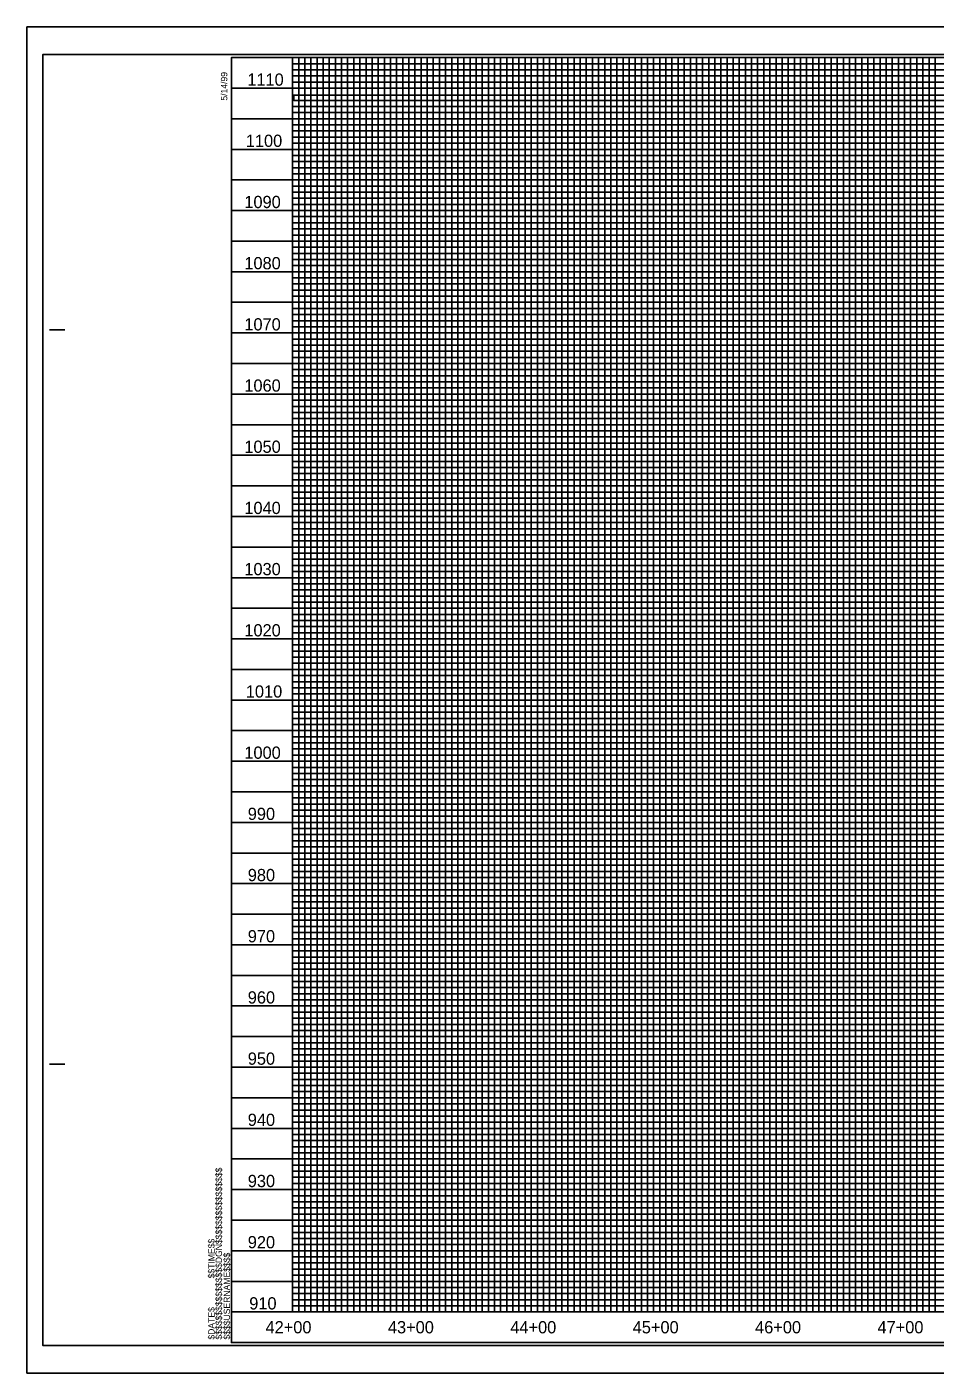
# Model space of a CAD drawing. Extents: x 1263639 to 1265460, y 747271 to 748371.
# Drawn here: x 1263639 to 1264381, y 747271 to 748371 of the extents above; entities that cross this region are included whole.
import ezdxf

# ---------------------------------------------------------------- set-up
doc = ezdxf.new("R2010")
doc.units = 0
for name, color, linetype in [('Pattern 1', 7, 'Continuous'), ('Pattern 2', 7, 'Continuous'), ('Prop Drainage Structure Bridge Opening', 7, 'Continuous'), ('Prop Grid Mask', 7, 'Continuous'), ('Prop Horizontal Alignment Curve and Spiral Data', 7, 'Continuous'), ('Prop Paved Shoulder', 7, 'Continuous'), ('Prop PFL Text', 7, 'Continuous'), ('Prop Roadway Bridge', 7, 'Continuous'), ('Prop Terminator CELL', 7, 'Continuous'), ('Prop Vertical Profile Strip Grade', 7, 'Continuous'), ('Prop VPI Label', 7, 'Continuous'), ('Sheet Sticker Exception Certification CELL', 7, 'Continuous')]:
    doc.layers.add(name, color=color, linetype=linetype)

msp = doc.modelspace()

# ---------------------------------------------------------------- linework, layer by layer
at = {"layer": 'Pattern 1'}
for points in [[(1263805.8, 748345.7), (1263855.8, 748345.7), (1263855.8, 747320.7), (1263905.8, 747320.7), (1263905.8, 748345.7), (1263955.8, 748345.7), (1263955.8, 747320.7), (1264005.8, 747320.7), (1264005.8, 748345.7), (1264055.8, 748345.7), (1264055.8, 747320.7), (1264105.8, 747320.7), (1264105.8, 748345.7), (1264155.8, 748345.7), (1264155.8, 747320.7), (1264205.8, 747320.7), (1264205.8, 748345.7), (1264255.8, 748345.7), (1264255.8, 747320.7), (1264305.8, 747320.7), (1264305.8, 748345.7), (1264355.8, 748345.7), (1264355.8, 747320.7), (1264405.8, 747320.7)], [(1265105.7, 748270.7), (1263805.9, 748270.7), (1263805.9, 748320.7), (1265005.8, 748320.7)], [(1265305.8, 748170.7), (1263805.8, 748170.7), (1263805.8, 748220.7), (1265105.7, 748220.7)], [(1265305.8, 748070.7), (1263805.8, 748070.7), (1263805.8, 748120.7), (1265305.8, 748120.7)], [(1265305.8, 747970.7), (1263805.8, 747970.7), (1263805.8, 748020.7), (1265305.8, 748020.7)], [(1265305.8, 747870.7), (1263805.8, 747870.7), (1263805.8, 747920.7), (1265305.8, 747920.7)], [(1265305.8, 747770.7), (1263805.8, 747770.7), (1263805.8, 747820.7), (1265305.8, 747820.7)], [(1265305.8, 747670.7), (1263805.8, 747670.7), (1263805.8, 747720.7), (1265305.8, 747720.7)], [(1265305.8, 747570.7), (1263805.8, 747570.7), (1263805.8, 747620.7), (1265305.8, 747620.7)], [(1265305.8, 747470.7), (1263805.8, 747470.7), (1263805.8, 747520.7), (1265305.8, 747520.7)], [(1265305.8, 747370.7), (1263805.8, 747370.7), (1263805.8, 747420.7), (1265305.8, 747420.7)]]:
    msp.add_lwpolyline(points, dxfattribs=at)
at = {"layer": 'Pattern 2'}
for points in [[(1263880.8, 747320.7), (1263880.8, 748345.7), (1263930.8, 748345.7), (1263930.8, 747320.7), (1263980.8, 747320.7), (1263980.8, 748345.7), (1264030.8, 748345.7), (1264030.8, 747320.7), (1264080.8, 747320.7), (1264080.8, 748345.7), (1264130.8, 748345.7), (1264130.8, 747320.7), (1264180.8, 747320.7), (1264180.8, 748345.7), (1264230.8, 748345.7), (1264230.8, 747320.7), (1264280.8, 747320.7), (1264280.8, 748345.7), (1264330.8, 748345.7), (1264330.8, 747320.7), (1264380.8, 747320.7), (1264380.8, 748345.7), (1264430.8, 748345.7)], [(1263805.8, 748295.7), (1265105.7, 748295.7)], [(1265105.7, 748245.7), (1263805.8, 748245.7), (1263805.8, 748195.7), (1265105.7, 748195.7)], [(1265305.8, 748145.7), (1263805.8, 748145.7), (1263805.8, 748095.7), (1265305.8, 748095.7)], [(1265305.8, 748045.7), (1263805.8, 748045.7), (1263805.8, 747995.7), (1265305.8, 747995.7)], [(1265305.8, 747945.7), (1263805.8, 747945.7), (1263805.8, 747895.7), (1265305.8, 747895.7)], [(1265305.8, 747845.7), (1263805.8, 747845.7), (1263805.8, 747795.7), (1265305.8, 747795.7)], [(1265305.8, 747745.7), (1263805.8, 747745.7), (1263805.8, 747695.7), (1265305.8, 747695.7)], [(1265305.8, 747645.7), (1263805.8, 747645.7), (1263805.8, 747595.7), (1265305.8, 747595.7)], [(1265305.8, 747545.7), (1263805.8, 747545.7), (1263805.8, 747495.7), (1265305.8, 747495.7)], [(1265305.8, 747445.7), (1263805.8, 747445.7), (1263805.8, 747395.7), (1265305.8, 747395.7)], [(1265305.8, 747345.7), (1263805.8, 747345.7)]]:
    msp.add_lwpolyline(points, dxfattribs=at)
at = {"layer": 'Prop Drainage Structure Bridge Opening'}
for p, q in [((1265322.8, 748370.7), (1263638.8, 748370.7)), ((1263638.8, 748370.7), (1263638.8, 747270.7)), ((1263638.8, 747270.7), (1265322.8, 747270.7))]:
    msp.add_line(p, q, dxfattribs=at)
at = {"layer": 'Prop Grid Mask'}
msp.add_lwpolyline([(1263855.8, 748345.7), (1265105.7, 748345.7), (1265105.8, 747320.7), (1263855.8, 747320.7)], close=True, dxfattribs=at)
at = {"layer": 'Prop Paved Shoulder'}
for p, q in [((1263657.3, 748123.2), (1263669.8, 748123.2)), ((1263657.3, 747523.2), (1263669.8, 747523.2)), ((1265305.8, 747320.7), (1263805.8, 747320.7)), ((1263805.8, 747295.7), (1263805.8, 747295.7)), ((1263805.8, 747295.7), (1263805.8, 747295.7)), ((1263805.8, 747295.7), (1263805.8, 747295.7)), ((1263805.8, 747295.7), (1263805.8, 747295.7)), ((1263805.8, 747295.7), (1263805.8, 747295.7)), ((1263805.8, 747295.7), (1263805.8, 747295.7))]:
    msp.add_line(p, q, dxfattribs=at)
msp.add_lwpolyline([(1265305.8, 748345.7), (1263805.8, 748345.7), (1263805.8, 747295.7), (1265305.8, 747295.7)], close=True, dxfattribs=at)
msp.add_lwpolyline([(1263843.3, 747295.7), (1263843.3, 747295.7)], dxfattribs=at)
at = {"layer": 'Prop PFL Text'}
for p, q in [((1263855.8, 748345.7), (1263855.8, 747320.7)), ((1263905.8, 748345.7), (1263905.8, 747320.7)), ((1263955.8, 748345.7), (1263955.8, 747320.7)), ((1264005.8, 748345.7), (1264005.8, 747320.7)), ((1264055.8, 748345.7), (1264055.8, 747320.7)), ((1264105.8, 748345.7), (1264105.8, 747320.7)), ((1264155.8, 748345.7), (1264155.8, 747320.7)), ((1264205.8, 748345.7), (1264205.8, 747320.7)), ((1264255.8, 748345.7), (1264255.8, 747320.7)), ((1264305.8, 748345.7), (1264305.8, 747320.7)), ((1264355.8, 748345.7), (1264355.8, 747320.7)), ((1263805.8, 748320.7), (1265005.8, 748320.7)), ((1263805.8, 748270.7), (1265105.7, 748270.7)), ((1263805.8, 748220.7), (1265105.7, 748220.7)), ((1263805.8, 748170.7), (1265305.8, 748170.7)), ((1263805.8, 748120.7), (1265305.8, 748120.7)), ((1263805.8, 748070.7), (1265305.8, 748070.7)), ((1263805.8, 748020.7), (1265305.8, 748020.7)), ((1263805.8, 747970.7), (1265305.8, 747970.7)), ((1263805.8, 747920.7), (1265305.8, 747920.7)), ((1263805.8, 747870.7), (1265305.8, 747870.7)), ((1263805.8, 747820.7), (1265305.8, 747820.7)), ((1263805.8, 747770.7), (1265305.8, 747770.7)), ((1263805.8, 747720.7), (1265305.8, 747720.7)), ((1263805.8, 747670.7), (1265305.8, 747670.7)), ((1263805.8, 747620.7), (1265305.8, 747620.7)), ((1263805.8, 747570.7), (1265305.8, 747570.7)), ((1263805.8, 747520.7), (1265305.8, 747520.7)), ((1263805.8, 747470.7), (1265305.8, 747470.7)), ((1263805.8, 747420.7), (1265305.8, 747420.7)), ((1263805.8, 747370.7), (1265305.8, 747370.7))]:
    msp.add_line(p, q, dxfattribs=at)
at = {"layer": 'Prop Roadway Bridge'}
msp.add_line((1263805.8, 747295.7), (1263805.8, 747295.7), dxfattribs=at)
at = {"layer": 'Prop Terminator CELL'}
msp.add_lwpolyline([(1265318.3, 748348.3), (1263651.8, 748348.3), (1263651.8, 747293.2), (1265318.3, 747293.2)], close=True, dxfattribs=at)
at = {"layer": 'Prop VPI Label'}
msp.add_lwpolyline([(1265322.8, 748370.7), (1263638.8, 748370.7), (1263638.8, 747270.7), (1265322.8, 747270.7)], close=True, dxfattribs=at)
at = {"layer": 'Sheet Sticker Exception Certification CELL'}
for p, q in [((1265255.8, 748165.7), (1263855.8, 748165.7)), ((1263855.8, 748165.7), (1263855.8, 748160.7)), ((1263855.8, 748160.7), (1265255.8, 748160.7)), ((1265255.8, 748140.7), (1263855.8, 748140.7))]:
    msp.add_line(p, q, dxfattribs=at)
for points in [[(1263860.8, 748345.7), (1263865.8, 748345.7), (1263870.8, 748345.7), (1263875.8, 748345.7), (1263885.8, 748345.7), (1263852.7, 748345.7), (1263857.7, 748345.7), (1263815.8, 748345.7), (1263820.8, 748345.7), (1263825.8, 748345.7), (1263835.8, 748345.7), (1263840.8, 748345.7), (1263845.8, 748345.7), (1263850.8, 748345.7), (1263860.8, 748345.7), (1263860.8, 747320.7), (1263865.8, 747320.7), (1263865.8, 748345.7), (1263870.8, 748345.7), (1263870.8, 747320.7), (1263875.8, 747320.7), (1263875.8, 748345.7), (1263885.8, 748345.7), (1263885.8, 747320.7), (1263890.8, 747320.7), (1263890.8, 748345.7), (1263895.8, 748345.7), (1263895.8, 747320.7), (1263900.8, 747320.7), (1263900.8, 748345.7), (1263910.8, 748345.7), (1263910.8, 747320.7), (1263915.8, 747320.7), (1263915.8, 748345.7), (1263920.8, 748345.7), (1263920.8, 747320.7), (1263925.8, 747320.7), (1263925.8, 748345.7), (1263935.8, 748345.7), (1263935.8, 747320.7), (1263940.8, 747320.7), (1263940.8, 748345.7), (1263945.8, 748345.7), (1263945.8, 747320.7), (1263950.8, 747320.7), (1263950.8, 748345.7), (1263960.8, 748345.7), (1263960.8, 747320.7), (1263965.8, 747320.7), (1263965.8, 748345.7), (1263970.8, 748345.7), (1263970.8, 747320.7), (1263975.8, 747320.7), (1263975.8, 748345.7), (1263985.8, 748345.7), (1263985.8, 747320.7), (1263990.8, 747320.7), (1263990.8, 748345.7), (1263995.8, 748345.7), (1263995.8, 747320.7), (1264000.8, 747320.7), (1264000.8, 748345.7), (1264010.8, 748345.7), (1264010.8, 747320.7), (1264015.8, 747320.7), (1264015.8, 748345.7), (1264020.8, 748345.7), (1264020.8, 747320.7)], [(1264020.8, 747320.7), (1264025.8, 747320.7), (1264025.8, 748345.7), (1264035.8, 748345.7), (1264035.8, 747320.7), (1264040.8, 747320.7), (1264040.8, 748345.7), (1264045.8, 748345.7), (1264045.8, 747320.7), (1264050.8, 747320.7), (1264050.8, 748345.7), (1264060.8, 748345.7), (1264060.8, 747320.7), (1264065.8, 747320.7), (1264065.8, 748345.7), (1264065.8, 748345.7), (1264070.8, 748345.7), (1264070.8, 747320.7), (1264075.8, 747320.7), (1264075.8, 748345.7), (1264085.8, 748345.7), (1264085.8, 747320.7), (1264090.8, 747320.7), (1264090.8, 748345.7), (1264095.8, 748345.7), (1264095.8, 747320.7), (1264100.8, 747320.7), (1264100.8, 748345.7), (1264110.8, 748345.7), (1264110.8, 747320.7), (1264115.8, 747320.7), (1264115.8, 748345.7), (1264120.8, 748345.7), (1264120.8, 747320.7), (1264125.8, 747320.7), (1264125.8, 748345.7), (1264135.8, 748345.7), (1264135.8, 747320.7), (1264140.8, 747320.7), (1264140.8, 748345.7), (1264145.8, 748345.7), (1264145.8, 747320.7), (1264150.8, 747320.7), (1264150.8, 748345.7), (1264160.8, 748345.7), (1264160.8, 747320.7), (1264165.8, 747320.7), (1264165.8, 748345.7), (1264170.8, 748345.7), (1264170.8, 747320.7), (1264175.8, 747320.7), (1264175.8, 748345.7), (1264185.8, 748345.7), (1264185.8, 747320.7), (1264200.8, 747320.7), (1264200.8, 748345.7), (1264210.8, 748345.7), (1264210.8, 747320.7), (1264215.8, 747320.7), (1264215.8, 748345.7), (1264220.8, 748345.7), (1264220.8, 747320.7), (1264225.8, 747320.7), (1264225.8, 748345.7), (1264235.8, 748345.7), (1264235.8, 747320.7), (1264240.8, 747320.7), (1264240.8, 748345.7), (1264245.8, 748345.7), (1264245.8, 747320.7), (1264250.8, 747320.7), (1264250.8, 748345.7), (1264260.8, 748345.7), (1264260.8, 747320.7), (1264265.8, 747320.7), (1264265.8, 748345.7), (1264270.8, 748345.7), (1264270.8, 747320.7), (1264275.8, 747320.7), (1264275.8, 748345.7), (1264285.8, 748345.7), (1264285.8, 747320.7), (1264290.8, 747320.7), (1264290.8, 748345.7), (1264295.8, 748345.7), (1264295.8, 747320.7), (1264300.8, 747320.7), (1264300.8, 748345.7), (1264310.8, 748345.7), (1264310.8, 747320.7), (1264315.8, 747320.7), (1264315.8, 748345.7), (1264320.8, 748345.7), (1264320.8, 747320.7), (1264325.8, 747320.7), (1264325.8, 748345.7), (1264335.8, 748345.7), (1264335.8, 747320.7)], [(1264190.8, 748345.7), (1264190.8, 747320.7), (1264195.8, 747320.7), (1264195.8, 748345.7)], [(1264190.8, 748345.1), (1264190.8, 747320.7), (1264195.8, 747320.7), (1264195.8, 748345.1)], [(1264340.8, 748345.7), (1264340.8, 747320.7), (1264345.8, 747320.7), (1264345.8, 748345.7), (1264350.8, 748345.7), (1264350.8, 747320.7), (1264360.8, 747320.7), (1264360.8, 748345.7), (1264365.8, 748345.7), (1264365.8, 747320.7), (1264370.8, 747320.7), (1264370.8, 748345.7), (1264375.8, 748345.7), (1264375.8, 747320.7)], [(1265005.8, 748340.7), (1263855.8, 748340.7), (1263855.8, 748335.7), (1265005.8, 748335.7)], [(1265005.8, 748330.7), (1263855.8, 748330.7), (1263855.8, 748325.7), (1265005.8, 748325.7)], [(1265005.8, 748315), (1263856.8, 748315), (1263856.8, 748310.7), (1265005.8, 748310.7)], [(1265005.8, 748305.7), (1263855.8, 748305.7), (1263855.8, 748300.7), (1265005.8, 748300.7)], [(1265105.7, 748290.7), (1263855.8, 748290.7), (1263855.8, 748285.7), (1265105.7, 748285.7)], [(1265105.7, 748280.7), (1263855.8, 748280.7), (1263855.8, 748275.7), (1265105.7, 748275.7)], [(1265105.7, 748265.7), (1263855.8, 748265.7), (1263855.8, 748260.7), (1265105.7, 748260.7)], [(1265105.7, 748255.7), (1263855.8, 748255.7), (1263855.8, 748250.7), (1265105.7, 748250.7)], [(1265105.7, 748240.7), (1263855.8, 748240.7), (1263855.8, 748235.7), (1265105.7, 748235.7)], [(1265105.7, 748230.7), (1263855.8, 748230.7), (1263855.8, 748225.7), (1265105.7, 748225.7)], [(1265105.7, 748215.7), (1263855.8, 748215.7), (1263855.8, 748210.7), (1265105.7, 748210.7)], [(1265105.7, 748205.7), (1263855.8, 748205.7), (1263855.8, 748205.7), (1263855.8, 748185.7), (1265105.7, 748185.7)], [(1263855.8, 748200.7), (1265105.7, 748200.7)], [(1265105.7, 748190.7), (1263855.8, 748190.7)], [(1265255.8, 748180.7), (1263855.8, 748180.7), (1263855.8, 748175.7), (1265255.8, 748175.7)], [(1265255.8, 748155.7), (1263855.8, 748155.7), (1263855.8, 748150.7), (1265255.8, 748150.7)], [(1265255.8, 748135.7), (1263855.8, 748135.7), (1263855.8, 748130.7), (1265255.8, 748130.7)], [(1265255.8, 748125.7), (1263855.8, 748125.7)], [(1263855.8, 748115.7), (1265255.8, 748115.7)], [(1265255.8, 748110.7), (1263855.8, 748110.7), (1263855.8, 748105.7), (1265255.8, 748105.7)], [(1265255.8, 748100.7), (1263855.8, 748100.7), (1263855.8, 748090.7), (1265255.8, 748090.7)], [(1265255.8, 748085.7), (1263855.8, 748085.7), (1263855.8, 748080.7), (1265255.8, 748080.7)], [(1265255.8, 748075.7), (1263855.8, 748075.7), (1263855.8, 748065.7), (1265255.8, 748065.7)], [(1265255.8, 748060.7), (1263855.8, 748060.7), (1263855.8, 748055.7), (1265255.8, 748055.7)], [(1265255.8, 748050.7), (1263855.8, 748050.7), (1263855.8, 748040.7), (1265255.8, 748040.7)], [(1265255.8, 748035.7), (1263855.8, 748035.7), (1263855.8, 748030.7), (1265255.8, 748030.7)], [(1265255.8, 748025.7), (1263855.8, 748025.7), (1263855.8, 748015.7), (1265255.8, 748015.7)], [(1265255.8, 748010.7), (1263855.8, 748010.7), (1263855.8, 748005.7), (1265255.8, 748005.7)], [(1265255.8, 748000.7), (1263855.8, 748000.7), (1263855.8, 747990.7), (1265255.8, 747990.7)], [(1265255.8, 747985.7), (1263855.8, 747985.7), (1263855.8, 747980.7), (1265255.8, 747980.7)], [(1265255.8, 747975.7), (1263855.8, 747975.7), (1263855.8, 747965.7), (1265255.8, 747965.7)], [(1265255.8, 747960.7), (1263855.8, 747960.7), (1263855.8, 747955.7), (1265255.8, 747955.7)], [(1265255.8, 747950.7), (1263855.8, 747950.7), (1263855.8, 747940.7), (1265255.8, 747940.7)], [(1265255.8, 747935.7), (1263855.8, 747935.7), (1263855.8, 747930.7), (1265255.8, 747930.7)], [(1265255.8, 747925.7), (1263855.8, 747925.7), (1263855.8, 747915.7), (1265255.8, 747915.7)], [(1265255.8, 747910.7), (1263855.8, 747910.7), (1263855.8, 747905.7), (1265255.8, 747905.7)], [(1265255.8, 747900.7), (1263855.8, 747900.7), (1263855.8, 747890.7), (1265255.8, 747890.7)], [(1265255.8, 747885.7), (1263855.8, 747885.7), (1263855.8, 747880.7), (1265255.8, 747880.7)], [(1265255.8, 747875.7), (1263855.8, 747875.7), (1263855.8, 747865.7), (1265255.8, 747865.7)], [(1265255.8, 747860.7), (1263855.8, 747860.7), (1263855.8, 747855.7), (1265255.8, 747855.7)], [(1265255.8, 747850.7), (1263855.8, 747850.7), (1263855.8, 747840.7), (1265255.8, 747840.7)], [(1265255.8, 747835.7), (1263855.8, 747835.7), (1263855.8, 747830.7), (1265255.8, 747830.7)], [(1265255.8, 747825.7), (1263855.8, 747825.7)], [(1263855.8, 747815.7), (1265255.8, 747815.7)], [(1265255.8, 747810.7), (1263855.8, 747810.7), (1263855.8, 747805.7), (1265255.8, 747805.7)], [(1265255.8, 747800.7), (1263855.8, 747800.7), (1263855.8, 747790.7), (1265255.8, 747790.7)], [(1265255.8, 747785.7), (1263855.8, 747785.7), (1263855.8, 747780.7), (1265255.8, 747780.7)], [(1265255.8, 747775.7), (1263855.8, 747775.7), (1263855.8, 747765.7), (1265255.8, 747765.7)], [(1265255.8, 747760.7), (1263855.8, 747760.7), (1263855.8, 747755.7), (1265255.8, 747755.7)], [(1265255.8, 747750.7), (1263855.8, 747750.7), (1263855.8, 747740.7), (1265255.8, 747740.7)], [(1265255.8, 747735.7), (1263855.8, 747735.7), (1263855.8, 747730.7), (1265255.8, 747730.7)], [(1265255.8, 747725.7), (1263855.8, 747725.7), (1263855.8, 747715.7), (1265255.8, 747715.7)], [(1265255.8, 747710.7), (1263855.8, 747710.7), (1263855.8, 747705.7), (1265255.8, 747705.7)], [(1265255.8, 747700.7), (1263855.8, 747700.7), (1263855.8, 747690.7), (1265255.8, 747690.7)], [(1265255.8, 747685.7), (1263855.8, 747685.7), (1263855.8, 747680.7), (1265255.8, 747680.7)], [(1265255.8, 747675.7), (1263855.8, 747675.7), (1263855.8, 747665.7), (1265255.8, 747665.7)], [(1265255.8, 747660.7), (1263855.8, 747660.7), (1263855.8, 747655.7), (1265255.8, 747655.7)], [(1265255.8, 747650.7), (1263855.8, 747650.7), (1263855.8, 747640.7), (1265255.8, 747640.7)], [(1265255.8, 747635.7), (1263855.8, 747635.7), (1263855.8, 747630.7), (1265255.8, 747630.7)], [(1265255.8, 747625.7), (1263855.8, 747625.7), (1263855.8, 747615.7), (1265255.8, 747615.7)], [(1265255.8, 747610.7), (1263855.8, 747610.7), (1263855.8, 747605.7), (1265255.8, 747605.7)], [(1265255.8, 747600.7), (1263855.8, 747600.7), (1263855.8, 747590.7), (1265255.8, 747590.7)], [(1265255.8, 747585.7), (1263855.8, 747585.7), (1263855.8, 747580.7), (1265255.8, 747580.7)], [(1265255.8, 747575.7), (1263855.8, 747575.7), (1263855.8, 747565.7), (1265255.8, 747565.7)], [(1265255.8, 747560.7), (1263855.8, 747560.7), (1263855.8, 747555.7), (1265255.8, 747555.7)], [(1265255.8, 747550.7), (1263855.8, 747550.7), (1263855.8, 747540.7), (1265255.8, 747540.7)], [(1265255.8, 747535.7), (1263855.8, 747535.7), (1263855.8, 747530.7), (1265255.8, 747530.7)], [(1265255.8, 747525.7), (1263855.8, 747525.7)], [(1263855.8, 747515.7), (1265255.8, 747515.7)], [(1265255.8, 747510.7), (1263855.8, 747510.7), (1263855.8, 747505.7), (1265255.8, 747505.7)], [(1265255.8, 747500.7), (1263855.8, 747500.7)], [(1263855.8, 747490.7), (1265255.8, 747490.7)], [(1265255.8, 747485.7), (1263855.8, 747485.7), (1263855.8, 747480.7), (1265255.8, 747480.7)], [(1265255.8, 747475.7), (1263855.8, 747475.7), (1263855.8, 747465.7), (1265255.8, 747465.7)], [(1265255.8, 747460.7), (1263855.8, 747460.7), (1263855.8, 747455.7), (1265255.8, 747455.7)], [(1265255.8, 747450.7), (1263855.8, 747450.7), (1263855.8, 747440.7), (1265255.8, 747440.7)], [(1265255.8, 747435.7), (1263855.8, 747435.7), (1263855.8, 747430.7), (1265255.8, 747430.7)], [(1265255.8, 747425.7), (1263855.8, 747425.7), (1263855.8, 747415.7), (1265255.8, 747415.7)], [(1265255.8, 747410.7), (1263855.8, 747410.7), (1263855.8, 747405.7), (1265255.8, 747405.7)], [(1265255.8, 747400.7), (1263855.8, 747400.7), (1263855.8, 747390.7), (1265255.8, 747390.7)], [(1265255.8, 747385.7), (1263855.8, 747385.7), (1263855.8, 747380.7), (1265255.8, 747380.7)], [(1265255.8, 747375.7), (1263855.8, 747375.7), (1263855.8, 747365.7), (1265255.8, 747365.7)], [(1265255.8, 747360.7), (1263855.8, 747360.7), (1263855.8, 747355.7), (1265255.8, 747355.7)], [(1265255.8, 747350.7), (1263855.8, 747350.7), (1263855.8, 747340.7), (1265255.8, 747340.7)], [(1265255.8, 747335.7), (1263855.8, 747335.7), (1263855.8, 747330.7), (1265255.8, 747330.7)], [(1265255.8, 747325.7), (1263855.8, 747325.7)]]:
    msp.add_lwpolyline(points, dxfattribs=at)

# ---------------------------------------------------------------- texts
at = {"layer": 'Prop Horizontal Alignment Curve and Spiral Data'}
for s, p in [('42+00', (1263833.7, 747303.2)), ('43+00', (1263933.7, 747303.2)), ('44+00', (1264033.7, 747303.2)), ('45+00', (1264133.7, 747303.2)), ('46+00', (1264233.7, 747303.2)), ('47+00', (1264333.7, 747303.2))]:
    msp.add_text(s, height=10, dxfattribs=at).set_placement(p)
at = {"layer": 'Prop Paved Shoulder'}
msp.add_text('5/14/99', height=5.25, rotation=90, dxfattribs=at).set_placement((1263802.5, 748310.5))
at = {"layer": 'Prop Roadway Bridge'}
for s, p in [('$$$$$$$$$$$$$$$$DGN$$$$$$$$$$$$$$$$', (1263798.1, 747298.1)), ('$$TIME$$', (1263792.1, 747348.1)), ('$$$$USERNAME$$$$', (1263804.7, 747298.1)), ('$DATE$', (1263792.1, 747298.1))]:
    msp.add_text(s, height=5.25, rotation=90, dxfattribs=at).set_placement(p)
at = {"layer": 'Prop Vertical Profile Strip Grade'}
for s, p in [('1110', (1263818.8, 748322.7)), ('1100', (1263817.6, 748272.7)), ('1090', (1263816.4, 748222.7)), ('1080', (1263816.4, 748172.7)), ('1070', (1263816.4, 748122.7)), ('1060', (1263816.4, 748072.7)), ('1050', (1263816.4, 748022.7)), ('1040', (1263816.4, 747972.7)), ('1030', (1263816.4, 747922.7)), ('1020', (1263816.4, 747872.7)), ('1010', (1263817.6, 747822.7)), ('1000', (1263816.4, 747772.7)), ('990', (1263819.2, 747722.7)), ('980', (1263819.2, 747672.7)), ('970', (1263819.2, 747622.7)), ('960', (1263819.2, 747572.7)), ('950', (1263819.2, 747522.7)), ('940', (1263819.2, 747472.7)), ('930', (1263819.2, 747422.7)), ('920', (1263819.2, 747372.7)), ('910', (1263820.4, 747322.7))]:
    msp.add_text(s, height=10, dxfattribs=at).set_placement(p)

doc.saveas('drawing.dxf')
